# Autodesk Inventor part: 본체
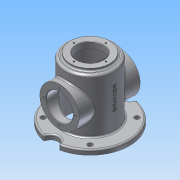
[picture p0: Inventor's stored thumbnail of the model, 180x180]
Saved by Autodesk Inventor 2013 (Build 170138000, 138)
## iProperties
Created: 2018-04
Part Number: 본체
Material: 알루미늄 6061
Document SubType Name: Modeling
Designer: Administrator
Density: 2.71 g/cm^3
Mass: 1151.24 g
Surface Area: 1200.36 cm^2
Volume: 424.812 cm^3
Author: Administrator
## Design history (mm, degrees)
sketch "스케치1"
  geometry: L1 (0, 0)-(50, 0); L2 (50, 0)-(50, 8); L3 (50, 8)-(80, 8); L4 (80, 8)-(80, 18); L5 (80, 18)-(50, 18); L6 (50, 18)-(50, 128); L7 (50, 128)-(40, 128); L8 (40, 128)-(40, 133); L9 (40, 133)-(0, 133); L10 (0, 133)-(0, 0)
  constraints: 20 end point, 6 parallel, 2 collinear, 2 perpendicular, 1 horizontal
  dimensions: "d9" = 100 diameter of L6 L10; "d12" = 160 diameter of L4 L10; "d13" = 80 diameter of L8 L10; "d14" = 10 distance between parallel lines of L3 L5; "d15" = 8 distance between parallel lines of L1 L3; "d16" = 125 distance between parallel lines of L3 L9; "d17" = 110 distance between parallel lines of L5 L7
revolve "회전1" sketch "스케치1" stored, may be unused: angle "d18" = 90 deg
hole "구멍1" diameter "d21" = 54; stored, may be unused: countersink angle "d25" = 90 deg, drill point angle "d27" = 118 deg; dims "d19" = 10, "d20" = 10, "d22" = 6, "d23" = 90, "d24" = 120, "d26" = 8
sketch "스케치2"
  geometry: C1 r 27 at (0, 0) reference; 1 further point
  constraints: 1 vertical alignment
  dimensions: "d28" = 32.5 distance of C1.centre point (0, 32.5)
hole "구멍2" sketch "스케치2" at (0, 32.5) diameter "d29" = 3.242; stored, may be unused: countersink angle "d33" = 90 deg, drill point angle "d35" = 118 deg; dims "d30" = 8, "d31" = 90, "d32" = 120, "d34" = 10
node "작업 평면1"
sketch "스케치3"
  geometry: L1 (8, 80)-(8, -80) reference; C1 r 40 at (68, 0); 1 further point
  constraints: 1 centre point, 1 horizontal alignment
  dimensions: "d40" = 80 diameter of C1; "d41" = 60 distance from line of C1.centre L1
extrude "돌출1" join sketch "스케치3" stored distance "d42" = 10; taper "d43" = 0 deg
hole "구멍3" diameter "d46" = 54; stored, may be unused: countersink angle "d50" = 90 deg, drill point angle "d52" = 118 deg; dims "d44" = 10, "d45" = 10, "d47" = 8, "d48" = 90, "d49" = 120, "d51" = 10
sketch "스케치4"
  geometry: C1 r 27 at (0, 0) reference; 2 further points
  constraints: 1 vertical alignment
  dimensions: "d53" = 32.5 distance of C1.centre point (0, 32.5)
hole "구멍4" sketch "스케치4" at (0, 32.5) diameter "d54" = 3.242; stored, may be unused: countersink angle "d58" = 90 deg, drill point angle "d60" = 118 deg; dims "d55" = 8, "d56" = 90, "d57" = 120, "d59" = 10
sketch "스케치5"
  geometry: L1 (0, 0)-(-67.5, 0); L2 (0, 0)-(-47.73, 47.73); C1 r 50 at (0, 0) reference; A1 r 67.5 centre (0, 0) between (-67.5, 0) and (-47.73, 47.73); 1 further point
  constraints: 4 end point, 2 coincident, 2 point on circle, 1 centre point, 1 horizontal
  dimensions: "d64" = 135 diameter of A1; "d65" = 45 deg angle of L1 L2
hole "구멍5" sketch "스케치5" at (-47.73, 47.73) diameter "d67" = 10; stored, may be unused: countersink angle "d71" = 90 deg, drill point angle "d73" = 118 deg; dims "d68" = 8, "d69" = 90, "d70" = 120, "d72" = 10
sketch "스케치6"
  geometry: L1 (0, 0)-(-80, 0); C1 r 50 at (0, 0) reference; C2 r 15 at (-80, 0); 1 further point
  constraints: 2 end point, 1 centre point, 1 coincident, 1 horizontal, 1 horizontal alignment, 1 other
  dimensions: "d77" = 30 diameter of C2
extrude "돌출2" cut sketch "스케치6" stored distance "d78" = 10; taper "d79" = 0 deg
node "작업 평면2"
sketch "스케치7"
  geometry: L1 (-78.594, 8)-(78.594, 8) reference; 2 further points
  constraints: 1 vertical alignment, 1 other
  dimensions: "d81" = 70 distance from line of L1 point (0, 78)
feature "엠보싱1" sketch "스케치7" dims "d9" = 100, "d12" = 160, "d13" = 80, "d14" = 10, "d15" = 8, "d16" = 125, "d17" = 110, "d82" = 0.5, "d83" = 0
fillet "모깎기1" dims "d84" = 3
fillet "모깎기2" dims "d85" = 5
fillet "모깎기3" dims "d86" = 3
fillet "모깎기4" dims "d87" = 3
chamfer "모따기1" distance "d88" = 1; stored, may be unused: second distance "d89" = 2, angle "d90" = 45 deg
fillet "모깎기5" dims "d91" = 3
node "솔리드1"
pattern_circular "원형 패턴1" dims angle "d37" = 360 deg
mirror "대칭1"
pattern_circular "원형 패턴2" dims angle "d62" = 360 deg
mirror "대칭2"
pattern_circular "원형 패턴3" dims angle "d75" = 360 deg
mirror "대칭3"
other parameters: "d39" = 62, "d80" = 130.25
